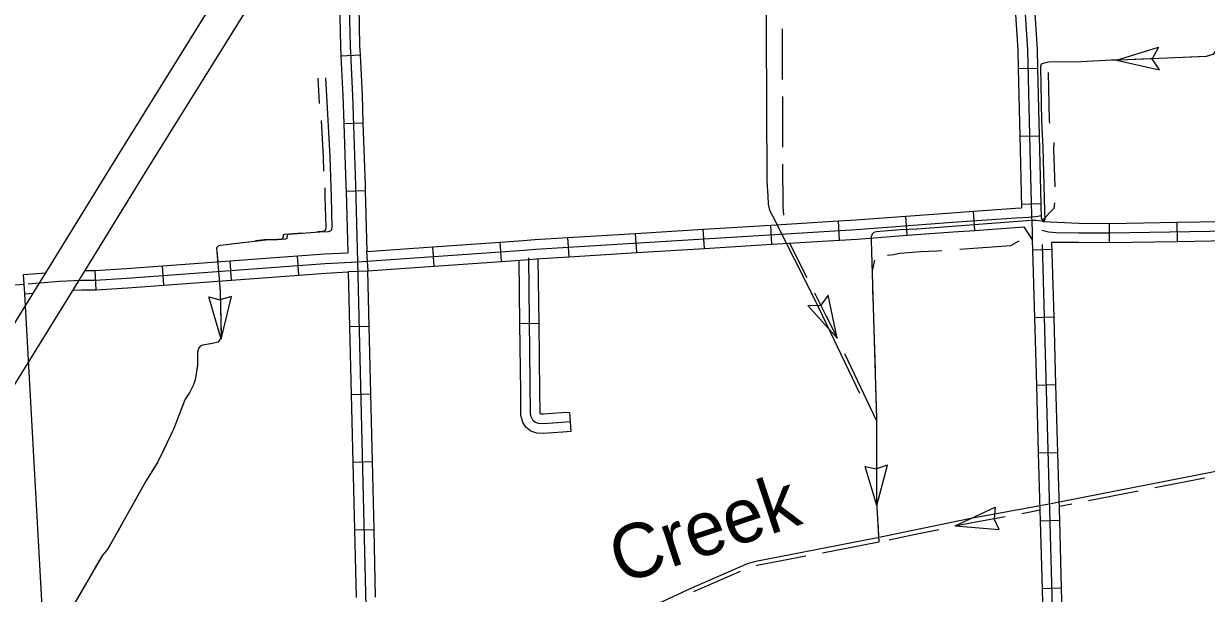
# Model space of a CAD drawing. Extents: x 1164457 to 1439835, y 1590918 to 1773502.
# Drawn here: x 1258762 to 1267982, y 1625786 to 1630223 of the extents above; entities that cross this region are included whole.
import ezdxf

# ---------------------------------------------------------------- set-up
doc = ezdxf.new("R2010")
doc.units = 0
for name, color, linetype in [('Level 15', 7, 'Continuous'), ('Level 32', 7, 'Continuous'), ('Level 34', 7, 'Continuous'), ('Level 43', 7, 'Continuous'), ('Level 45', 7, 'Continuous'), ('Level 6', 7, 'Continuous')]:
    doc.layers.add(name, color=color, linetype=linetype)

msp = doc.modelspace()

# ---------------------------------------------------------------- linework, layer by layer
at = {"layer": 'Level 15'}
for points in [[(1253993.2, 1619805.1), (1254506.1, 1620766.5), (1256186.5, 1623773.6), (1257379.6, 1625774), (1258934.5, 1628282.8), (1259494.9, 1629192.9), (1260659.4, 1631068)], [(1260872.2, 1630936.8), (1259707.6, 1629061.4), (1259147.2, 1628151.4), (1257593.2, 1625644.1), (1256403.1, 1623648.5), (1254725.5, 1620646.6), (1254211.9, 1619684)]]:
    msp.add_lwpolyline(points, dxfattribs=at)
at = {"layer": 'Level 32'}
for p, q in [((1261234.9, 1629972.8), (1261384.7, 1629980.1)), ((1266515.5, 1629873.7), (1266665.5, 1629877.2)), ((1261257.2, 1629446.4), (1261407.1, 1629451.5)), ((1266527.9, 1629345.8), (1266677.9, 1629349.3)), ((1261274.9, 1628919.2), (1261424.8, 1628923.3)), ((1266541.1, 1628817.8), (1266691, 1628821.7)), ((1265122.5, 1628537.3), (1265113.2, 1628687)), ((1265650.1, 1628574.8), (1265639, 1628724.4)), ((1266176.3, 1628613.1), (1266165.9, 1628762.7)), ((1263541.5, 1628439.8), (1263532.2, 1628589.5)), ((1264068.5, 1628472.3), (1264059.2, 1628622)), ((1264595.5, 1628504.8), (1264586.2, 1628654.5)), ((1267226.3, 1628517.8), (1267227.7, 1628667.8)), ((1267756.2, 1628526.9), (1267753.7, 1628676.8)), ((1262488.3, 1628371.3), (1262477.9, 1628521)), ((1263014.5, 1628407.3), (1263005.2, 1628557)), ((1260908.3, 1628265.2), (1260897.2, 1628414.8)), ((1261448.5, 1628298.6), (1261438, 1628448.3)), ((1261961.6, 1628334.5), (1261951.2, 1628484.1)), ((1266780, 1628464.4), (1266630, 1628460.2)), ((1259855.2, 1628186.9), (1259844.1, 1628336.5)), ((1260381.7, 1628226), (1260370.6, 1628375.6)), ((1259327.5, 1628150.7), (1259318.2, 1628300.4)), ((1261292, 1628294), (1261442, 1628298.2)), ((1261302.4, 1627863.8), (1261452.4, 1627867.4)), ((1266794.8, 1627936.7), (1266644.8, 1627932.4)), ((1266809.6, 1627408.9), (1266659.6, 1627404.7)), ((1261315.2, 1627335.9), (1261465.1, 1627339.6)), ((1266824.4, 1626881.1), (1266674.4, 1626876.9)), ((1261327.9, 1626808.1), (1261477.9, 1626811.7)), ((1261340.7, 1626280.3), (1261490.6, 1626283.9)), ((1266839.2, 1626353.3), (1266689.2, 1626349.1)), ((1266854, 1625825.5), (1266704, 1625821.3))]:
    msp.add_line(p, q, dxfattribs=at)
for points in [[(1266507, 1634098.2), (1266526.7, 1632945.6), (1266532.7, 1632605.8), (1266554, 1632003.8), (1266554.6, 1631412.9), (1266570.2, 1630297.1), (1266587.1, 1630019.9), (1266607.9, 1629132.9), (1266618.4, 1628729.6), (1266623.3, 1628614.4), (1266625.4, 1628539.1)], [(1261295.4, 1630547.9), (1261306.2, 1630051), (1261324.9, 1629664.4), (1261348.7, 1628964), (1261365.2, 1628368), (1261458.8, 1624497.4), (1261503, 1623132.1), (1261505.5, 1623067.7), (1261501.7, 1623041.2), (1261495.4, 1623009.6), (1261481.5, 1622985.6), (1261466, 1622969.5), (1261449.4, 1622961.7), (1261391.9, 1622953.3), (1261142.6, 1622941.1), (1260938.5, 1622942), (1258950.1, 1622854.5), (1257949.9, 1622809.2), (1257180.1, 1622788.2), (1256671, 1622766), (1256306.3, 1622746.2), (1255487.8, 1622688.9), (1251482.4, 1622430.4), (1250992.3, 1622408.6)], [(1261221.4, 1630502.6), (1261231.3, 1630048.4), (1261234.9, 1629972.8)], [(1261371.4, 1630505.9), (1261381.2, 1630053.6), (1261384.7, 1629980.1)], [(1266493.7, 1630401.8), (1266495.2, 1630294.3), (1266512.1, 1630016.7), (1266515.5, 1629873.7)], [(1266643.7, 1630403.9), (1266645.2, 1630299.9), (1266662, 1630023), (1266665.5, 1629877.2)], [(1261234.9, 1629972.8), (1261249.9, 1629661.3), (1261257.2, 1629446.4)], [(1261384.7, 1629980.1), (1261399.8, 1629667.5), (1261407.1, 1629451.5)], [(1266665.5, 1629877.2), (1266677.9, 1629349.3)], [(1266515.5, 1629873.7), (1266527.9, 1629345.8)], [(1261257.2, 1629446.4), (1261273.7, 1628961.7), (1261274.9, 1628919.2)], [(1261407.1, 1629451.5), (1261423.6, 1628966.4), (1261424.8, 1628923.3)], [(1266527.9, 1629345.8), (1266533, 1629131.1), (1266541.8, 1628788.5)], [(1266677.9, 1629349.3), (1266682.9, 1629134.8), (1266693.9, 1628708.4)], [(1266700.7, 1628614.4), (1266752, 1628602.4), (1266809, 1628596.5), (1266986.6, 1628595.1), (1267229.5, 1628592.8), (1271437.7, 1628665.1), (1272120.6, 1628669.6), (1273147.1, 1628683.5), (1273289.1, 1628692), (1273392.2, 1628702.1), (1273469.9, 1628703.8), (1274983.9, 1628729.6), (1276197.2, 1628751.6), (1277109.4, 1628786.7), (1277542.5, 1628816), (1277761.5, 1628824.8), (1278261.9, 1628855.5), (1279090.5, 1628894.2), (1280163.9, 1628927.4), (1282110.7, 1629023.3), (1282767, 1629058.8)], [(1261274.9, 1628919.2), (1261288.2, 1628439.3)], [(1261424.8, 1628923.3), (1261438, 1628448.3)], [(1266165.9, 1628762.7), (1266495.2, 1628785.6), (1266541.8, 1628788.5)], [(1258795.8, 1628197.1), (1259040.8, 1628217.1), (1259212.5, 1628224.1), (1259319.6, 1628225.3), (1259565.4, 1628240.6), (1261113, 1628355.6), (1261365.2, 1628368), (1262663.1, 1628458.7), (1262751.3, 1628466.2), (1265254.7, 1628620.6), (1266002.1, 1628676.1), (1266500.1, 1628710.8), (1266595.5, 1628716.7), (1266652.6, 1628721.3), (1266695.8, 1628729.6)], [(1264586.2, 1628654.5), (1265113.2, 1628687)], [(1265113.2, 1628687), (1265249.7, 1628695.4), (1265639, 1628724.4)], [(1265639, 1628724.4), (1265996.7, 1628750.9), (1266165.9, 1628762.7)], [(1266693.9, 1628708.4), (1266711, 1628683.1)], [(1266711, 1628683.1), (1266987.2, 1628670.1), (1267227.7, 1628667.8)], [(1267753.7, 1628676.8), (1268281.6, 1628685.9)], [(1263005.2, 1628557), (1263532.2, 1628589.5)], [(1263532.2, 1628589.5), (1264059.2, 1628622)], [(1264059.2, 1628622), (1264586.2, 1628654.5)], [(1265650.1, 1628574.8), (1266007.4, 1628601.3), (1266176.3, 1628613.1)], [(1266176.3, 1628613.1), (1266559.4, 1628639.7), (1266627.8, 1628538.1)], [(1267227.8, 1628667.8), (1267229.2, 1628667.8), (1267753.7, 1628676.8)], [(1261951.2, 1628484.1), (1262477.9, 1628521)], [(1262477.9, 1628521), (1262657.3, 1628533.5), (1262745.8, 1628541), (1263005.2, 1628557)], [(1264068.5, 1628472.3), (1264595.5, 1628504.8)], [(1264595.5, 1628504.8), (1265122.5, 1628537.3)], [(1265122.5, 1628537.3), (1265259.8, 1628545.8), (1265650.1, 1628574.8)], [(1266630, 1628460.2), (1266627.8, 1628538.1)], [(1266852.6, 1623184.4), (1266828.1, 1624073.7), (1266703.8, 1628503.4)], [(1266794.8, 1627936.7), (1266778.4, 1628521.8)], [(1266778.4, 1628521.8), (1266985.9, 1628520.1), (1267226.3, 1628517.8)], [(1267226.3, 1628517.8), (1267229.8, 1628517.8), (1267756.2, 1628526.9)], [(1267756.2, 1628526.9), (1268284.2, 1628535.9)], [(1260370.6, 1628375.6), (1260897.2, 1628414.8)], [(1260897.2, 1628414.8), (1261108.4, 1628430.5), (1261288.2, 1628439.3)], [(1261438, 1628448.3), (1261951.2, 1628484.1)], [(1262488.3, 1628371.3), (1262668.9, 1628383.9), (1262756.8, 1628391.4), (1263014.5, 1628407.3)], [(1263014.5, 1628407.3), (1263541.5, 1628439.8)], [(1263541.5, 1628439.8), (1264068.5, 1628472.3)], [(1266644.8, 1627932.4), (1266630, 1628460.2)], [(1259318.2, 1628300.4), (1259560.3, 1628315.4), (1259844.1, 1628336.5)], [(1259844.1, 1628336.5), (1260370.6, 1628375.6)], [(1261442, 1628298.2), (1261961.6, 1628334.5)], [(1261961.6, 1628334.5), (1262488.3, 1628371.3)], [(1258770.1, 1628119.8), (1258761.8, 1628269.6), (1258935.1, 1628283.7)], [(1259238.3, 1628299.4), (1259316.8, 1628300.3), (1259318.2, 1628300.4)], [(1259855.2, 1628186.9), (1260381.7, 1628226)], [(1260381.7, 1628226), (1260908.3, 1628265.2)], [(1260908.3, 1628265.2), (1261117.6, 1628280.7), (1261292.1, 1628289.3)], [(1261292.1, 1628289.3), (1261302.4, 1627863.8)], [(1261442, 1628298.2), (1261452.4, 1627867.4)], [(1258770.1, 1628119.8), (1258836.8, 1628125.2)], [(1259144, 1628146.2), (1259214.5, 1628149.1), (1259322.3, 1628150.3), (1259327.5, 1628150.7)], [(1259327.5, 1628150.7), (1259570.5, 1628165.8), (1259855.2, 1628186.9)], [(1261302.4, 1627863.8), (1261315.2, 1627335.9)], [(1261452.4, 1627867.4), (1261465.1, 1627339.6)], [(1266659.6, 1627404.7), (1266644.8, 1627932.4)], [(1266809.6, 1627408.9), (1266794.8, 1627936.7)], [(1266674.4, 1626876.9), (1266659.6, 1627404.7)], [(1266824.4, 1626881.1), (1266809.6, 1627408.9)], [(1261315.2, 1627335.9), (1261327.9, 1626808.1)], [(1261465.1, 1627339.6), (1261477.9, 1626811.7)], [(1266689.2, 1626349.1), (1266674.4, 1626876.9)], [(1266839.2, 1626353.3), (1266824.4, 1626881.1)], [(1261327.9, 1626808.1), (1261340.7, 1626280.3)], [(1261477.9, 1626811.7), (1261490.6, 1626283.9)], [(1261490.6, 1626283.9), (1261503.4, 1625756)], [(1266704, 1625821.3), (1266689.2, 1626349.1)], [(1266854, 1625825.5), (1266839.2, 1626353.3)], [(1261340.7, 1626280.3), (1261353.4, 1625752.4)], [(1266718.9, 1625293.5), (1266704, 1625821.3)], [(1266868.8, 1625297.7), (1266854, 1625825.5)]]:
    msp.add_lwpolyline(points, dxfattribs=at)
at = {"layer": 'Level 34'}
msp.add_lwpolyline([(1254856.6, 1627925.9), (1256072.9, 1628010.1), (1256196.2, 1628021.8), (1257099.4, 1628083), (1257425.9, 1628102.7), (1258766, 1628195.1)], dxfattribs=at)
at = {"layer": 'Level 43'}
for p, q in [((1260301.2, 1627765.1), (1260204.9, 1628094.6)), ((1260204.9, 1628094.6), (1260293.7, 1628072.9)), ((1260382.5, 1628098.6), (1260294.9, 1628073)), ((1260301.2, 1627765.1), (1260382.5, 1628098.6)), ((1265033, 1628109.4), (1264976, 1628030.9)), ((1265103.5, 1627773.6), (1265033, 1628109.4)), ((1264874.5, 1628029.2), (1264976, 1628030.9)), ((1265103.5, 1627773.6), (1264874.5, 1628029.2)), ((1266024.7, 1626310.8), (1266334.7, 1626458.2)), ((1266334.7, 1626458.2), (1266327.4, 1626367.2)), ((1266024.7, 1626310.8), (1266366.8, 1626283.5)), ((1266366.8, 1626283.5), (1266327.6, 1626366))]:
    msp.add_line(p, q, dxfattribs=at)
for points in [[(1264546.1, 1631332.6), (1264554.8, 1628999.1), (1264562.7, 1628879.9), (1264565.7, 1628817.2), (1264575.3, 1628769.4), (1264599.6, 1628726.1), (1264930.2, 1628073.3), (1265278.7, 1627345.5)], [(1264674.9, 1630184), (1264676.3, 1629788.1)], [(1268082.3, 1630139.7), (1268080.8, 1630110.2), (1268069.5, 1630030.8), (1268033.6, 1629983.5), (1267980.6, 1629966.5), (1267809.5, 1629959.4)], [(1268033.6, 1629983.5), (1267980.6, 1629966.5), (1267309.5, 1629938.6), (1267243.4, 1629938.1), (1267005.2, 1629924.9), (1266755.3, 1629922.9), (1266718.4, 1629915.3), (1266694.8, 1629908.7), (1266689.1, 1629888.8), (1266698.1, 1629463.5), (1266708.5, 1629259.3), (1266720.8, 1628764.9), (1266722.6, 1628696.8), (1266713.8, 1628682.3), (1266658.3, 1628691.1), (1266615.8, 1628691.1), (1265726.5, 1628623), (1265601.5, 1628618), (1265435.7, 1628604.1), (1265411.8, 1628601.1), (1265390, 1628596.1), (1265378.1, 1628583.2), (1265370.1, 1628562.4), (1265368.6, 1628535.6), (1265410.8, 1627148.9), (1265410.9, 1626501), (1265429.4, 1626184.8)], [(1267282, 1629938.4), (1267609.5, 1630040.9), (1267560.7, 1629949)], [(1267150.1, 1629932.9), (1267005.2, 1629924.9), (1266755.3, 1629922.9), (1266754.4, 1629922.7)], [(1267282, 1629938.4), (1267616.9, 1629863.4), (1267560.7, 1629949)], [(1267479.8, 1629945.7), (1267309.5, 1629938.6), (1267282, 1629938.4)], [(1267677.6, 1629953.9), (1267479.8, 1629945.7)], [(1261055.3, 1629798.7), (1261066.3, 1629601)], [(1261114.2, 1629802.6), (1261148.3, 1629189.8), (1261158, 1628870.9), (1261164.3, 1628637.2), (1261162.9, 1628621.1), (1261155.4, 1628609.3), (1261135.6, 1628603.1), (1261070.8, 1628599.7)], [(1266749.5, 1629843.9), (1266757.4, 1629468.6), (1266758.5, 1629448)], [(1264676.8, 1629656.1), (1264678.3, 1629260.1)], [(1261081.5, 1629469.2), (1261097.3, 1629185.9), (1261100.7, 1629073.7)], [(1266792.1, 1629299), (1266791.6, 1629249.2), (1266800.3, 1628952.4)], [(1264678.8, 1629128.1), (1264680, 1628800), (1264684.5, 1628732.2)], [(1261108.6, 1628945.7), (1261110.9, 1628870.9), (1261117.1, 1628637.2), (1261115.8, 1628621.1), (1261108.3, 1628609.3), (1261088.4, 1628603.1), (1261052, 1628601.2)], [(1266798.2, 1628827.6), (1266794.1, 1628784.5), (1266706, 1628692)], [(1261070.8, 1628599.7), (1260825.1, 1628582.1), (1260817, 1628578.4), (1260813.9, 1628551.1), (1260803.9, 1628543.6), (1260741.7, 1628540.5), (1260669.7, 1628538.6), (1260297.4, 1628495.8), (1260281.9, 1628492), (1260265.7, 1628477.7), (1260292.7, 1628142.9)], [(1260936, 1628592.3), (1260793.6, 1628582.1), (1260785.6, 1628578.4), (1260782.5, 1628551.1), (1260772.5, 1628543.6), (1260710.3, 1628540.5), (1260638.3, 1628538.6), (1260568.7, 1628530.6)], [(1260469, 1628515.5), (1260297.4, 1628495.8), (1260281.9, 1628492), (1260265.7, 1628477.7), (1260274.5, 1628368.5)], [(1264731.8, 1628513.2), (1264867.2, 1628245.7)], [(1266521.5, 1628528), (1266454.9, 1628494), (1266060.1, 1628463.8)], [(1265722.6, 1628442.8), (1265591.4, 1628431.8), (1265567.6, 1628428.9), (1265545.8, 1628423.9), (1265496.6, 1628417.2)], [(1265920.3, 1628453.7), (1265882.2, 1628450.8), (1265757.3, 1628445.8), (1265722.6, 1628442.8)], [(1265394.1, 1628380.3), (1265375.9, 1628297.3), (1265383.3, 1628054.6)], [(1260292.7, 1628142.9), (1260300.4, 1627798.8), (1260294.7, 1627767.5), (1260278.6, 1627742.8), (1260234.8, 1627732.5), (1260155.6, 1627718.1), (1260138.5, 1627711.4), (1260126.2, 1627693.4), (1260117.8, 1627664.8), (1260117.6, 1627562.3), (1260097.7, 1627450.2), (1260084.4, 1627405.5), (1260056.8, 1627353.3), (1260018.4, 1627294.4), (1259931.5, 1627069.3), (1259880.7, 1626960.4), (1259808.5, 1626810.3), (1259713.6, 1626658.4), (1259450.2, 1626186.2), (1259414.1, 1626126.1), (1259376.1, 1626084), (1259085.5, 1625581.3)], [(1260291.2, 1628161), (1260292.7, 1628142.9), (1260301.2, 1627765.1)], [(1264926.9, 1628127.9), (1265016.3, 1627951.3)], [(1265016.3, 1627951.3), (1265055.3, 1627874.2), (1265103.5, 1627773.6)], [(1265387.3, 1627922.6), (1265399.3, 1627526.8)], [(1260176.4, 1627721.9), (1260155.6, 1627718.1), (1260138.5, 1627711.4), (1260126.2, 1627693.4), (1260117.8, 1627664.8), (1260117.6, 1627562.3), (1260116.8, 1627558)], [(1265160.5, 1627654.5), (1265411.4, 1627130.7)], [(1260116.8, 1627558), (1260097.7, 1627450.2), (1260084.4, 1627405.5), (1260064.8, 1627368.4)], [(1265403.3, 1627394.9), (1265410.8, 1627148.9), (1265410.8, 1626999)], [(1260002.4, 1627252.8), (1259931.5, 1627069.3), (1259880.7, 1626960.4), (1259846.4, 1626889.1)], [(1265410.9, 1626867), (1265410.9, 1626501), (1265412.7, 1626471.1)], [(1259784.9, 1626772.5), (1259713.6, 1626658.4), (1259586.2, 1626430.1)], [(1268174.5, 1626758.3), (1266757.6, 1626480.2), (1266132.9, 1626365.1), (1265418.6, 1626217.2), (1264469.8, 1626034.2), (1264419.9, 1626021.2), (1264398.3, 1626014.1), (1263967.1, 1625827.1), (1263525.4, 1625621.9)], [(1265412.7, 1626471.1), (1265321.4, 1626773.3), (1265410.9, 1626754.8)], [(1265412.7, 1626471.1), (1265497.6, 1626783.5), (1265410.9, 1626754.8)], [(1267969.3, 1626683.5), (1267580.7, 1626607.3)], [(1267451.2, 1626581.8), (1267062.6, 1626505.6)], [(1266933.1, 1626480.1), (1266836.2, 1626461.1)], [(1266414.2, 1626382.6), (1266143.7, 1626332.8), (1266025.2, 1626308.2)], [(1266686.9, 1626432.8), (1266544, 1626406.5)], [(1259521.9, 1626314.8), (1259450.2, 1626186.2), (1259414.1, 1626126.1), (1259376.1, 1626084), (1259315.1, 1625978.5)], [(1265420.4, 1626339.3), (1265429.4, 1626184.8)], [(1265896, 1626281.5), (1265702.1, 1626241.3)], [(1265702.1, 1626241.3), (1265508.2, 1626201.2)], [(1265429.4, 1626184.8), (1264990, 1626100.1)], [(1264860.4, 1626075.1), (1264480.6, 1626001.8), (1264471.7, 1625999.5)], [(1264347.7, 1625955.2), (1263984.4, 1625797.6)], [(1259249, 1625864.2), (1259085.5, 1625581.3), (1259081.7, 1625562.3), (1259083.6, 1625553.7), (1259124.6, 1625555.3)]]:
    msp.add_lwpolyline(points, dxfattribs=at)
at = {"layer": 'Level 45'}
for p, q in [((1262780.3, 1627887.1), (1262630.3, 1627885.3)), ((1263018.5, 1627195.5), (1263028.1, 1627045.8))]:
    msp.add_line(p, q, dxfattribs=at)
for points in [[(1262630.3, 1627885.3), (1262624.3, 1628380.2)], [(1263023.3, 1627120.7), (1262959.5, 1627116.6), (1262814.1, 1627106.3), (1262775.3, 1627108.5), (1262752.9, 1627115.5), (1262734.2, 1627130.7), (1262723.3, 1627149.3), (1262716.3, 1627171), (1262713.7, 1627184), (1262699.1, 1628399.1)], [(1262780.3, 1627887.1), (1262774.2, 1628392.4)], [(1262636.6, 1627357.4), (1262630.3, 1627885.3)], [(1262786.6, 1627359.2), (1262780.3, 1627887.1)], [(1263028.1, 1627045.8), (1262964.5, 1627041.8), (1262814.6, 1627031.2), (1262761.7, 1627034.2), (1262716.8, 1627048.2), (1262676.3, 1627081), (1262654.4, 1627118.5), (1262643.6, 1627152.1), (1262638.8, 1627176.1), (1262636.6, 1627357.4)], [(1263018.5, 1627195.5), (1262954.5, 1627191.4), (1262813.5, 1627181.5), (1262791.3, 1627182.7), (1262789, 1627190), (1262788.6, 1627191.9), (1262786.6, 1627359.2)]]:
    msp.add_lwpolyline(points, dxfattribs=at)
at = {"layer": 'Level 6'}
msp.add_lwpolyline([(1256316.6, 1624060.7), (1258926.4, 1624190.1), (1258913.1, 1625540.6), (1258770.1, 1628119.8)], dxfattribs=at)

# ---------------------------------------------------------------- texts
at = {"layer": 'Level 43'}
msp.add_text('Creek', height=422.4, rotation=18.36438, dxfattribs=at).set_placement((1263416.1, 1625855.1))

doc.saveas('drawing.dxf')
